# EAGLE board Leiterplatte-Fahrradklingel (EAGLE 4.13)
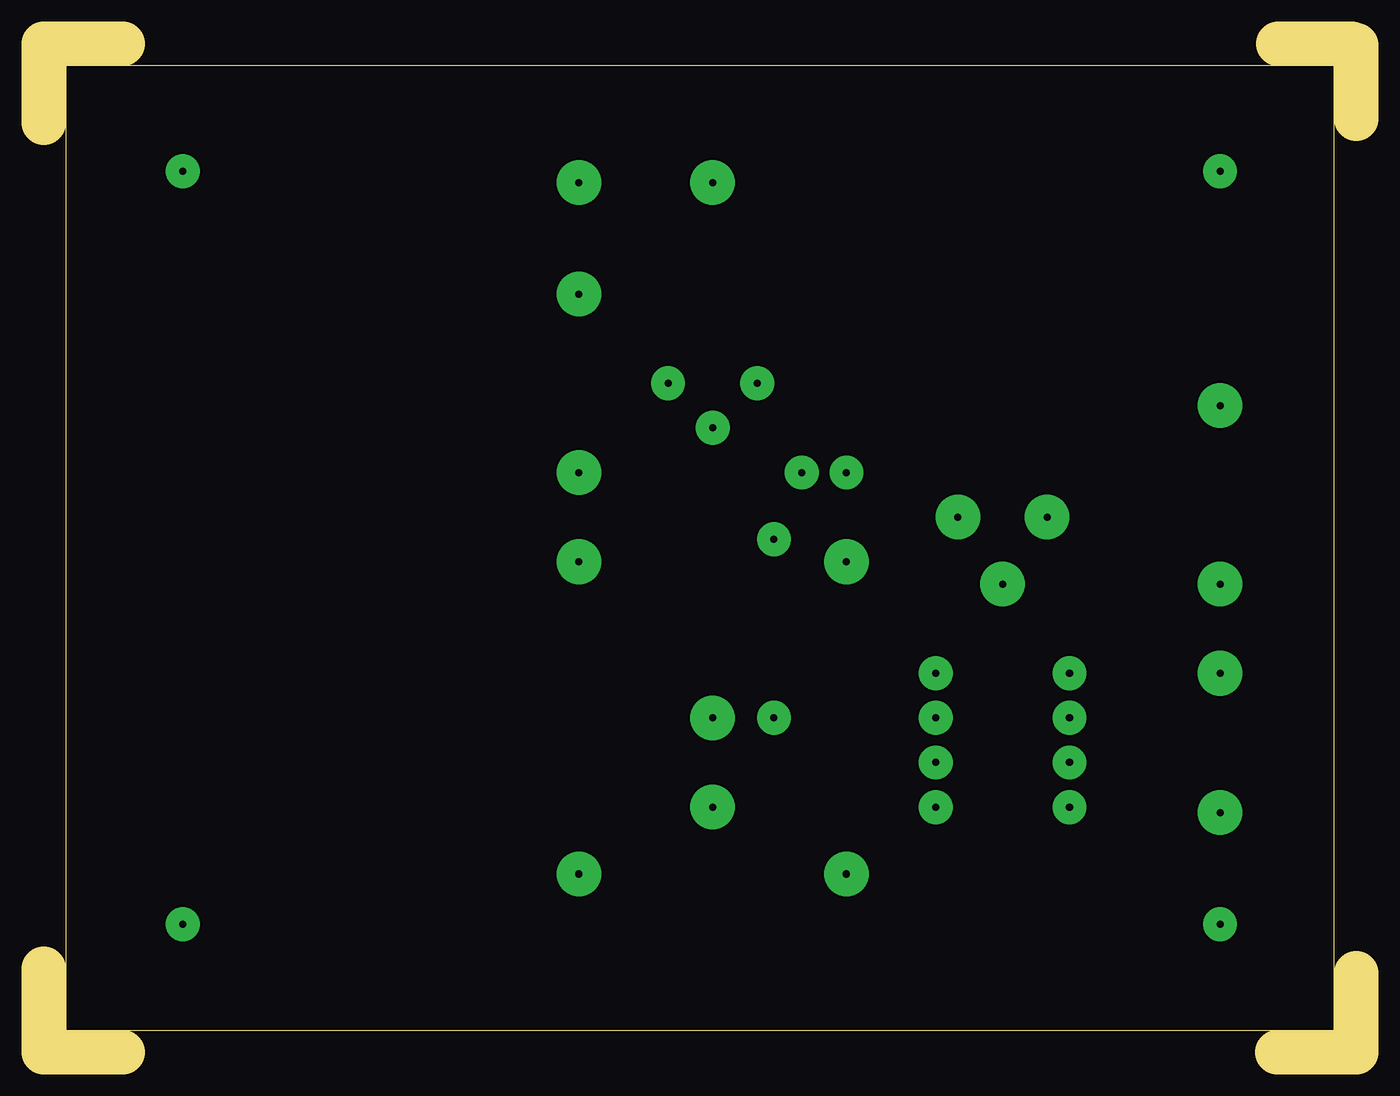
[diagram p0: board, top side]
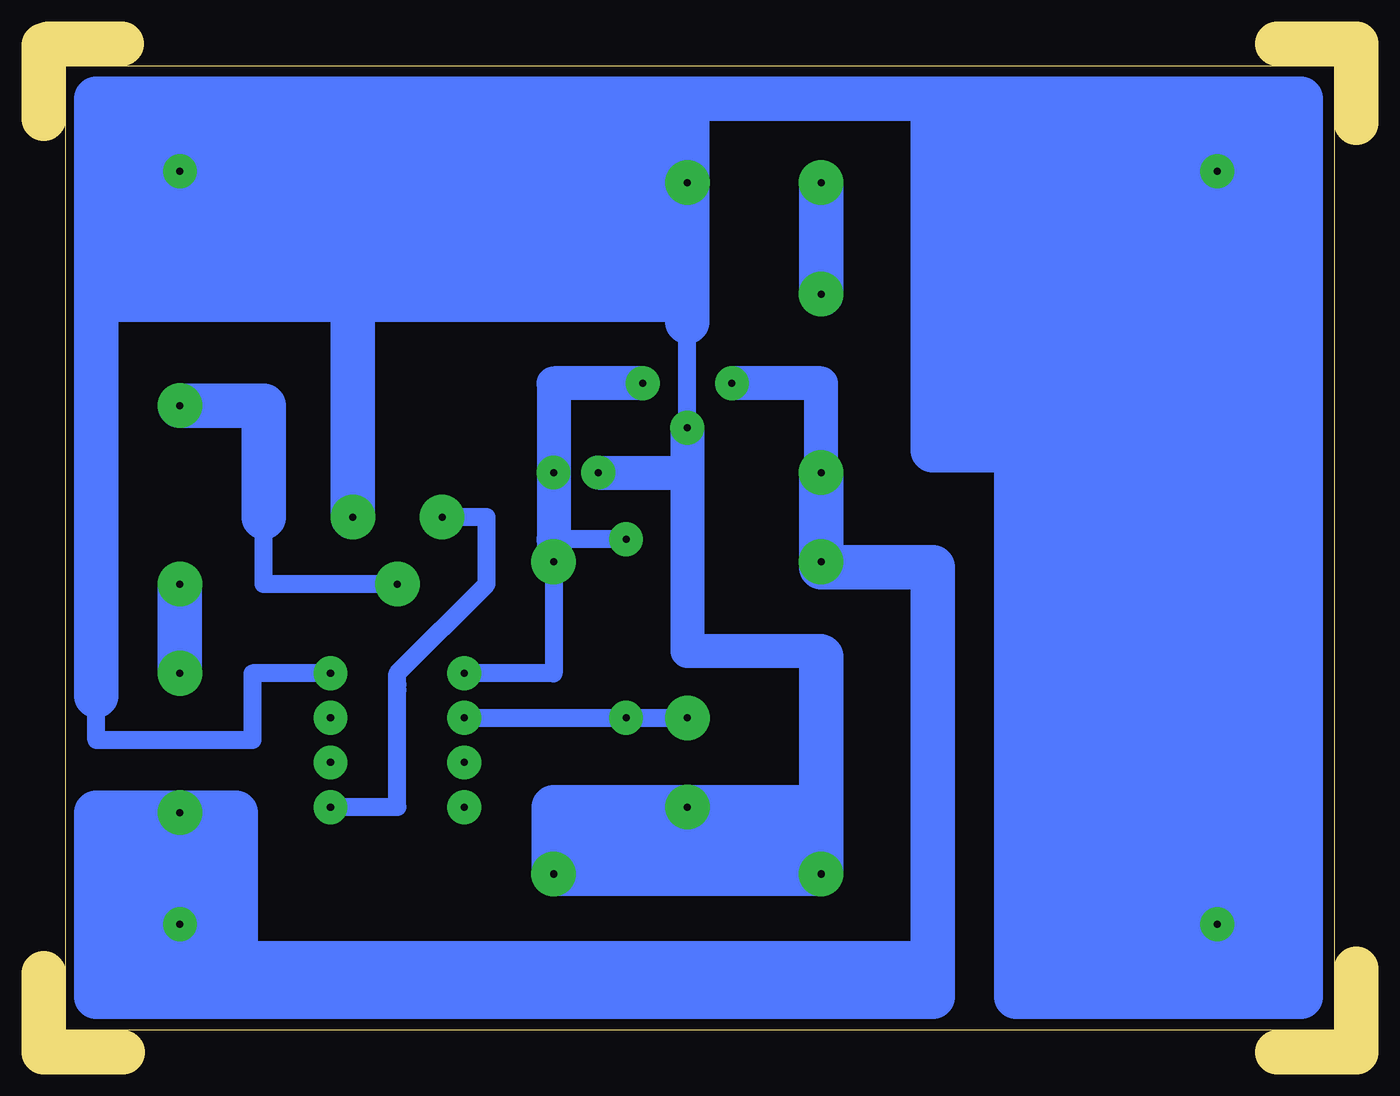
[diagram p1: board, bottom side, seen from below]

Size 74.72 x 57.41 mm. Coordinates in mm from the lower left corner, seen from the top.
Outline: 0,52.91 0,57.41 4.5,57.41
Outline: 0,0.25 0,4.75
Outline: 4.5,0 0,0
Outline: 74.72,57.34 74.72,53.16
Outline: 74.72,4.5 74.72,0 70.22,0
Outline: 70.29,57.41 74.47,57.41
Outline: 1.25,1.25 21.57,1.25 73.47,1.25 73.47,56.16 1.25,56.16 1.25,1.25
Copper layers (1*16): Top 0.035mm / dielectric 1.5mm / Bottom 0.035mm
Design rules "default": minimum track width 10mil, minimum drill 24mil, track to track 8mil, track to pad 8mil, pad to pad 8mil, via to via 8mil, smd to smd 8mil, copper to edge 40mil, drill to drill 8mil, minimum pad ring 10mil, minimum via ring 8mil, stop-mask expansion 4mil, vias tented up to drill 0mil, thermal gap 10mil

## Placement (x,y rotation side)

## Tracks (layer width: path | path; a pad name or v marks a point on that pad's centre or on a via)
S$1  (via drill 0.4 pad 1.93)
  other vias: 7.92,7.28
S$2  (via drill 0.4 pad 1.93)
  other vias: 7.92,50.15
S$3  (via drill 0.4 pad 1.93)
  other vias: 66.97,50.15
S$4  (via drill 0.4 pad 1.93)
  other vias: 66.97,7.28
S$5  (via drill 0.4 pad 2.54)
  Bottom 0.406: v30.46,49.51 v30.46,43.16
  Bottom 2.54: v30.46,49.51 v30.46,43.16
S$6  (via drill 0.4 pad 2.54)
  Bottom 0.406: v66.97,26.65 v66.97,21.57
  Bottom 2.54: v66.97,26.65 v66.97,21.57
S$7
  Bottom 2.54: 71.73,42.52 71.73,20.3
S$8  (via drill 0.4 pad 1.93, 0.4 pad 2.54)
  Bottom 0.406: v30.46,33 v30.46,27.92 24.11,27.92 24.11,5.06
  Bottom 1.93: v35.54,38.08 30.46,38.08 v30.46,33
  Bottom 2.54: v30.46,27.92 v30.46,33 | 30.46,27.6 24.11,27.6 24.11,5.06 | 71.73,11.09 71.73,3.16 24.11,3.16 24.11,5.06 | 71.73,11.09 71.73,12.68 | 24.11,5.06 64.12,5.06 | 71.73,11.09 71.73,13.63 v66.97,13.63 63.8,13.63 63.8,3.79
S$9  (via drill 0.4 pad 1.93, 0.4 pad 2.54)
  Bottom 0.406: 45.7,19.03 46.65,19.03 | 46.65,19.03 v50.78,19.03 | v38.08,19.03 v41.57,19.03 46.65,19.03
  Bottom 1.016: v50.78,19.03 v41.57,19.03 v38.08,19.03
S$11  (via drill 0.4 pad 1.93)
  other vias: 50.78,16.49
S$12  (via drill 0.4 pad 1.93)
  other vias: 50.78,13.95
S$13  (via drill 0.4 pad 1.93, 0.4 pad 2.54)
  Bottom 1.016: v45.7,27.92 45.7,21.57 v50.78,21.57 | v41.57,29.19 45.7,29.19
  Bottom 1.93: v40.62,38.08 45.7,38.08 v45.7,33 45.7,29.19 v45.7,27.92
S$14  (via drill 0.4 pad 1.93)
  other vias: 58.4,19.03
S$15  (via drill 0.4 pad 1.93)
  other vias: 58.4,16.49
S$16  (via drill 0.4 pad 1.93, 0.4 pad 2.54)
  Bottom 1.016: v58.4,13.95 54.59,13.95 54.59,20.62 | 54.59,20.62 54.59,20.93 | 54.59,20.62 54.59,21.57 49.51,26.65 49.51,30.46 v52.05,30.46
S$18  (via drill 0.4 pad 1.93)
  Bottom 1.016: v58.4,21.57 62.84,21.57 62.84,17.76 71.73,17.76 71.73,21.25
S$19  (via drill 0.4 pad 1.93, 0.4 pad 2.54)
  Bottom 0.406: 38.08,10.14 v45.7,10.14
  Bottom 1.016: v38.08,35.54 38.08,41.57 38.08,42.84 | v38.08,13.95 38.08,10.14 v30.46,10.14 v45.7,10.14
  Bottom 1.93: v38.08,35.54 38.08,33 | 38.08,33 38.08,22.84 30.46,22.84 30.78,13.95 v30.46,10.14 | v43.16,33 38.08,33
  Bottom 2.54: 38.08,54.27 v38.08,49.51 38.08,43.16 | 38.08,54.27 3.16,54.27 3.16,3.16 19.35,3.16 19.35,53.95 | 38.08,43.16 38.08,42.84 56.81,42.84 | 56.81,42.84 57.13,42.84 v57.13,30.46 | 38.08,43.16 38.08,41.57 | 30.78,13.95 v38.08,13.95 45.7,13.95 v45.7,10.14 v30.46,10.14 30.46,22.52 | 38.08,54.27 71.73,54.27 71.73,42.84 56.81,42.84
S$20  (via drill 0.4 pad 2.54)
  Bottom 1.016: v54.59,26.65 62.21,26.65 62.21,30.46 | 62.21,36.81 64.43,36.81
  Bottom 2.54: 64.43,36.81 v66.97,36.81 62.21,36.81 62.21,30.46
S$22
  Bottom 2.54: 19.66,34.27 24.11,34.27 24.11,53.95
(copper drawn outside any net)
  shapes: Bottom area x6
